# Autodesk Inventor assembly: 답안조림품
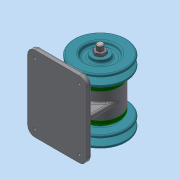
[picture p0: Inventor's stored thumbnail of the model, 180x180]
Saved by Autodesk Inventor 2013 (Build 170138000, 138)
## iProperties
Created: 2019-09
Part Number: 답안조림품
Document SubType Name: Assembly
Designer: Administrator
Author: Administrator
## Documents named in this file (10)
- C:\Users\Administrator\Desktop\490904V1021\답안조림품.iam
- C:\Users\Administrator\Desktop\490904V1021\본체.ipt
- C:\Users\Administrator\Desktop\490904V1021\V-벨트풀리.ipt
- C:\Users\Administrator\Desktop\490904V1021\너트 M10x1.ipt
- C:\Users\Administrator\Desktop\490904V1021\베어링 6004.ipt
- C:\Users\Administrator\Desktop\490904V1021\볼트 M4.ipt
- C:\Users\Administrator\Desktop\490904V1021\오일 실 17 30 5.ipt
- C:\Users\Administrator\Desktop\490904V1021\축.ipt
- C:\Users\Administrator\Desktop\490904V1021\커버.ipt
- C:\Users\Administrator\Desktop\490904V1021\키 5 x 5 x 12.ipt
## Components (2 placed, 1 different names)
1. V-벨트풀리:1
2. V-벨트풀리:2 — 각도:1
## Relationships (1: Angle 1)
- 각도:1 [Angle]: V-벨트풀리:2
